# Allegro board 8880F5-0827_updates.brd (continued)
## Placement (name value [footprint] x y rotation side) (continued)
NOREF#1969  -  []  165.8 185.42 90 top
NOREF#1970  -  []  284.36 272.1 90 top
NOREF#1971  -  []  339.65 265.86 90 top
NOREF#1972  -  []  184.47 173.11 0 top
NOREF#1973  -  []  165.8 158.5 0 top
NOREF#1974  -  []  166.06 216.47 90 top
NOREF#1975  -  []  272.55 245.18 0 top
NOREF#1976  -  []  419.4 171.64 0 top
NOREF#1977  -  []  302.32 144.15 0 top
NOREF#1978  -  []  378.33 209.11 0 top
NOREF#1979  -  []  250.74 224.72 0 top
NOREF#1980  -  []  327.25 265.55 0 top
NOREF#1981  -  []  298.13 274.06 0 top
NOREF#1982  -  []  201.91 172.56 90 top
NOREF#1983  -  []  167.7 215.35 90 top
NOREF#1984  -  []  303.15 211.32 90 top
NOREF#1985  -  []  263.31 164.74 0 top
NOREF#1986  -  []  184.47 219.75 90 top
NOREF#1987  -  []  221.56 171.46 0 top
NOREF#1988  -  []  352.24 243.59 90 top
NOREF#1989  -  []  312.42 146.05 0 top
NOREF#1990  -  []  194.09 173.86 90 top
NOREF#1991  -  []  451.64 179.06 0 top
NOREF#1992  -  []  271.34 182.64 0 top
NOREF#1993  -  []  309.21 187.61 0 top
NOREF#1994  -  []  109.96 238.84 0 top
NOREF#1995  -  []  330.74 164.72 0 top
NOREF#1996  -  []  100.73 238.84 0 top
NOREF#1997  -  []  167.7 187.92 90 top
NOREF#1998  -  []  115.61 219.13 90 top
NOREF#1999  -  []  468.01 171.53 0 top
NOREF#2000  -  []  254.61 205.86 90 top
NOREF#2001  -  []  230.43 188.88 0 top
NOREF#2002  -  []  275.12 271.65 90 top
NOREF#2003  -  []  326.43 288.31 90 top
NOREF#2004  -  []  329.85 164.74 0 top
NOREF#2005  -  []  346.27 132.97 90 top
NOREF#2006  -  []  295.96 248.49 0 top
NOREF#2007  -  []  262.04 164.74 0 top
NOREF#2008  -  []  200.98 255.15 90 top
NOREF#2009  -  []  230.73 193.69 0 top
NOREF#2010  -  []  450.03 182.17 0 top
NOREF#2011  -  []  383.09 273.11 0 top
NOREF#2012  -  []  328.42 129.74 90 top
NOREF#2013  -  []  118.45 234.24 90 top
NOREF#2014  -  []  331.62 205.55 0 top
NOREF#2015  -  []  342.04 164.72 0 top
NOREF#2016  -  []  259.65 265.86 90 top
NOREF#2017  -  []  471.21 175.95 90 top
NOREF#2018  -  []  306.92 154.05 0 top
NOREF#2019  -  []  463.61 171.53 0 top
NOREF#2020  -  []  182.57 240.28 0 top
NOREF#2021  -  []  216.96 180.71 0 top
NOREF#2022  -  []  259.33 205.55 0 top
NOREF#2023  -  []  115.99 130.36 90 top
NOREF#2024  -  []  334.29 204.35 90 top
NOREF#2025  -  []  463.11 186.77 0 top
NOREF#2026  -  []  237.66 224.74 0 top
NOREF#2027  -  []  124.1 238.84 0 top
NOREF#2028  -  []  343.2 232.26 90 top
NOREF#2029  -  []  330.73 264.35 90 top
NOREF#2030  -  []  419.9 288.57 90 top
NOREF#2031  -  []  248.96 224.74 0 top
NOREF#2032  -  []  247.25 265.56 90 top
NOREF#2033  -  []  396.55 241.11 0 top
NOREF#2034  -  []  184.89 254.6 90 top
NOREF#2035  -  []  106.76 215.26 0 top
NOREF#2036  -  []  239.33 176.03 0 top
NOREF#2037  -  []  165.8 144.78 0 top
NOREF#2038  -  []  192.47 168.6 90 top
NOREF#2039  -  []  209.49 177.76 90 top
NOREF#2040  -  []  312.67 146.1 90 top
NOREF#2041  -  []  226.83 209.63 90 top
NOREF#2042  -  []  312.79 288.86 90 top
NOREF#2043  -  []  339.65 264.65 90 top
NOREF#2044  -  []  418.37 289.17 90 top
NOREF#2045  -  []  352.25 243.59 90 top
NOREF#2046  -  []  351.34 245.18 0 top
NOREF#2047  -  []  333.33 241.33 90 top
NOREF#2048  -  []  209.49 168.6 90 top
NOREF#2049  -  []  468.85 257.36 90 top
NOREF#2050  -  []  398.53 178.25 90 top
NOREF#2051  -  []  230.73 249.2 0 top
NOREF#2052  -  []  249.6 223.52 90 top
NOREF#2053  -  []  310.73 253.69 0 top
NOREF#2054  -  []  396.55 225.11 0 top
NOREF#2055  -  []  344.37 128.27 0 top
NOREF#2056  -  []  471.59 130.36 90 top
NOREF#2057  -  []  264.29 143.19 0 top
NOREF#2058  -  []  332.51 205.55 0 top
NOREF#2059  -  []  334.29 205.56 90 top
NOREF#2060  -  []  272.55 249.5 0 top
NOREF#2061  -  []  226.27 216.63 90 top
NOREF#2062  -  []  185.2 276.04 90 top
NOREF#2063  -  []  175.7 218.65 90 top
NOREF#2064  -  []  378.75 256.66 90 top
NOREF#2065  -  []  108.01 222.33 0 top
NOREF#2066  -  []  320.42 131.64 0 top
NOREF#2067  -  []  192.47 259.8 90 top
NOREF#2068  -  []  418.37 241.16 90 top
NOREF#2069  -  []  555.66 300.54 90 top
NOREF#2070  -  []  310.83 224.63 0 top
NOREF#2071  -  []  165.8 212.85 0 top
NOREF#2072  -  []  392.47 272.56 90 top
NOREF#2073  -  []  254.29 205.56 0 top
NOREF#2074  -  []  333.33 181.33 90 top
NOREF#2075  -  []  253.4 265.56 0 top
NOREF#2076  -  []  249.15 296.86 0 top
NOREF#2077  -  []  352.25 249.18 90 top
NOREF#2078  -  []  310.73 249.2 0 top
NOREF#2079  -  []  329.85 224.74 0 top
NOREF#2080  -  []  201.23 219.75 90 top
NOREF#2081  -  []  369.38 257.11 0 top
NOREF#2082  -  []  199.84 175.58 90 top
NOREF#2083  -  []  93.76 271.33 90 top
NOREF#2084  -  []  250.18 182.88 0 top
NOREF#2085  -  []  423.71 181.22 90 top
NOREF#2086  -  []  263.31 224.74 0 top
NOREF#2087  -  []  351.34 249.5 0 top
NOREF#2088  -  []  405.93 272.56 90 top
NOREF#2089  -  []  313.77 146.05 90 top
NOREF#2090  -  []  310.73 193.69 0 top
NOREF#2091  -  []  229.51 243.41 0 top
NOREF#2092  -  []  175.7 205.19 90 top
NOREF#2093  -  []  199.59 230.19 90 top
NOREF#2094  -  []  259.59 133.29 90 top
NOREF#2095  -  []  267.84 280.1 0 top
NOREF#2096  -  []  224.65 211.67 0 top
NOREF#2097  -  []  310.41 188.88 90 top
NOREF#2098  -  []  118.74 215.34 0 top
NOREF#2099  -  []  298.13 214.06 0 top
NOREF#2100  -  []  165.8 199.39 90 top
NOREF#2101  -  []  265.64 280.1 0 top
NOREF#2102  -  []  237.98 163.82 90 top
NOREF#2103  -  []  412.6 161.74 0 top
NOREF#2104  -  []  199.33 240.28 90 top
NOREF#2105  -  []  184.47 229.07 90 top
NOREF#2106  -  []  284.36 280.1 0 top
NOREF#2107  -  []  450.03 166.93 0 top
NOREF#2108  -  []  201.23 242.78 90 top
NOREF#2109  -  []  263.71 288.86 0 top
NOREF#2110  -  []  262.36 223.82 90 top
NOREF#2111  -  []  220.36 237.06 0 top
NOREF#2112  -  []  400.34 194.68 90 top
NOREF#2113  -  []  93.02 247.21 90 top
NOREF#2114  -  []  309.51 253.69 0 top
NOREF#2115  -  []  259.33 204.35 90 top
NOREF#2116  -  []  252.6 296.86 0 top
NOREF#2117  -  []  264.29 280.1 0 top
NOREF#2118  -  []  230.41 248.88 90 top
NOREF#2119  -  []  175.8 228.97 90 top
NOREF#2120  -  []  331.54 192.73 90 top
NOREF#2121  -  []  271.34 181.37 0 top
NOREF#2122  -  []  328.96 164.74 0 top
NOREF#2123  -  []  392.47 288.67 90 top
NOREF#2124  -  []  332.51 265.56 90 top
NOREF#2125  -  []  388.43 180.15 0 top
NOREF#2126  -  []  226.83 269.63 90 top
NOREF#2127  -  []  399.67 139.89 0 top
NOREF#2128  -  []  328.96 164.72 0 top
NOREF#2129  -  []  371.48 257.11 0 top
NOREF#2130  -  []  263.63 163.82 90 top
NOREF#2131  -  []  479.44 239.09 0 top
NOREF#2132  -  []  333.72 205.86 90 top
NOREF#2133  -  []  101.82 271.33 90 top
NOREF#2134  -  []  451.68 230.2 0 top
NOREF#2135  -  []  402.06 217.61 0 top
NOREF#2136  -  []  222.11 240.71 0 top
NOREF#2137  -  []  456.08 214.96 0 top
NOREF#2138  -  []  266.49 143.19 0 top
NOREF#2139  -  []  371.73 273.11 0 top
NOREF#2140  -  []  320.94 211.63 90 top
NOREF#2141  -  []  385.19 241.11 0 top
NOREF#2142  -  []  375.73 196.98 90 top
NOREF#2143  -  []  380.53 217.11 0 top
NOREF#2144  -  []  334.29 265.56 0 top
NOREF#2145  -  []  366.88 222.7 0 top
NOREF#2146  -  []  475.04 239.09 0 top
NOREF#2147  -  []  247.89 204.35 90 top
NOREF#2148  -  []  387.39 297.12 0 top
NOREF#2149  -  []  106.76 222.88 0 top
NOREF#2150  -  []  485.36 257.36 90 top
NOREF#2151  -  []  331.94 204.65 90 top
NOREF#2152  -  []  249.6 224.74 90 top
NOREF#2153  -  []  411.09 146.88 90 top
NOREF#2154  -  []  317.83 197.63 0 top
NOREF#2155  -  []  406.44 154.88 0 top
NOREF#2156  -  []  397.55 209.41 90 top
NOREF#2157  -  []  378.75 224.05 90 top
NOREF#2158  -  []  107.02 179.19 0 top
NOREF#2159  -  []  182.82 243.9 90 top
NOREF#2160  -  []  378.58 273.11 90 top
NOREF#2161  -  []  511.59 293.82 90 top
NOREF#2162  -  []  312.21 131.64 0 top
NOREF#2163  -  []  418.37 273.42 90 top
NOREF#2164  -  []  208.98 259.8 90 top
NOREF#2165  -  []  168.69 292.55 90 top
NOREF#2166  -  []  385.32 178.25 90 top
NOREF#2167  -  []  241.6 296.61 0 top
NOREF#2168  -  []  215.96 237.06 0 top
NOREF#2169  -  []  220.36 248.49 0 top
NOREF#2170  -  []  167.7 145.93 90 top
NOREF#2171  -  []  106.18 160.58 90 top
NOREF#2172  -  []  410.78 131.89 0 top
NOREF#2173  -  []  473.79 196.21 0 top
NOREF#2174  -  []  105.58 234.24 90 top
NOREF#2175  -  []  177.33 133.47 90 top
NOREF#2176  -  []  420.62 287.22 90 top
NOREF#2177  -  []  182.57 144.78 90 top
NOREF#2178  -  []  182.82 203.01 90 top
NOREF#2179  -  []  251.86 192.43 90 top
NOREF#2180  -  []  263.95 223.52 90 top
NOREF#2181  -  []  403.41 209.61 0 top
NOREF#2182  -  []  305.83 204.31 0 top
NOREF#2183  -  []  401.87 139.89 0 top
NOREF#2184  -  []  185.2 292.55 90 top
NOREF#2185  -  []  453.88 171.53 0 top
NOREF#2186  -  []  342.36 165.04 90 top
NOREF#2187  -  []  311.15 159.63 90 top
NOREF#2188  -  []  392.73 188.15 0 top
NOREF#2189  -  []  342.04 224.74 0 top
NOREF#2190  -  []  182.82 175.58 90 top
NOREF#2191  -  []  230.43 194.01 0 top
NOREF#2192  -  []  184.47 176.66 90 top
NOREF#2193  -  []  396.55 289.12 0 top
NOREF#2194  -  []  111.54 287.84 90 top
NOREF#2195  -  []  128.05 273.87 90 top
NOREF#2196  -  []  167.7 132.72 0 top
NOREF#2197  -  []  272.25 184.23 0 top
NOREF#2198  -  []  392.73 154.88 0 top
NOREF#2199  -  []  200.98 256.5 90 top
NOREF#2200  -  []  310.41 247.61 90 top
NOREF#2201  -  []  328.33 187.93 0 top
NOREF#2202  -  []  388.66 139.89 0 top
NOREF#2203  -  []  399.39 178.25 0 top
NOREF#2204  -  []  175.7 209.49 90 top
NOREF#2205  -  []  230.41 188.88 90 top
NOREF#2206  -  []  273.09 288.31 90 top
NOREF#2207  -  []  352.24 182.32 90 top
NOREF#2208  -  []  472.86 210.36 90 top
NOREF#2209  -  []  320.94 151.63 90 top
NOREF#2210  -  []  383.09 224.85 0 top
NOREF#2211  -  []  101.82 273.87 90 top
NOREF#2212  -  []  327.15 286.96 90 top
NOREF#2213  -  []  155.57 275.14 90 top
NOREF#2214  -  []  468.01 214.96 0 top
NOREF#2215  -  []  297.83 174.63 90 top
NOREF#2216  -  []  225.83 204.31 0 top
NOREF#2217  -  []  248.33 247.93 0 top
NOREF#2218  -  []  461.86 225.6 90 top
NOREF#2219  -  []  118.33 273.87 90 top
NOREF#2220  -  []  338.2 246.67 0 top
NOREF#2221  -  []  201.49 176.66 90 top
NOREF#2222  -  []  369.38 241.11 0 top
NOREF#2223  -  []  310.73 189.2 0 top
NOREF#2224  -  []  397.8 179.6 90 top
NOREF#2225  -  []  460.93 234.74 90 top
NOREF#2226  -  []  331.62 204.35 90 top
NOREF#2227  -  []  201.23 227.72 90 top
NOREF#2228  -  []  451.68 195.91 0 top
NOREF#2229  -  []  167.7 134.07 90 top
NOREF#2230  -  []  320.83 194.63 0 top
NOREF#2231  -  []  239.33 183.63 90 top
NOREF#2232  -  []  411.26 163.19 90 top
NOREF#2233  -  []  409.17 281.37 0 top
NOREF#2234  -  []  117.33 247.35 90 top
NOREF#2235  -  []  318.3 164.74 90 top
NOREF#2236  -  []  250.74 164.72 0 top
NOREF#2237  -  []  379.73 271.21 90 top
NOREF#2238  -  []  465.45 292.92 90 top
NOREF#2239  -  []  209.33 215.25 90 top
NOREF#2240  -  []  403.41 209.61 0 top
NOREF#2241  -  []  306.85 271.67 0 top
NOREF#2242  -  []  322.62 139.64 0 top
NOREF#2243  -  []  392.24 199.18 90 top
NOREF#2244  -  []  386.53 181.42 90 top
NOREF#2245  -  []  339.33 265.55 0 top
NOREF#2246  -  []  230.73 243.41 0 top
NOREF#2247  -  []  528.1 257.36 90 top
NOREF#2248  -  []  263.83 231.63 90 top
NOREF#2249  -  []  119.76 127 90 top
NOREF#2250  -  []  423.2 146.88 0 top
NOREF#2251  -  []  334.61 264.65 90 top
NOREF#2252  -  []  483.04 239.09 0 top
NOREF#2253  -  []  415.1 163.64 0 top
NOREF#2254  -  []  201.23 201.89 90 top
NOREF#2255  -  []  411.26 179.6 90 top
NOREF#2256  -  []  250.74 224.74 0 top
NOREF#2257  -  []  352.55 242.64 0 top
NOREF#2258  -  []  177.33 187.32 90 top
NOREF#2259  -  []  409.17 297.12 0 top
NOREF#2260  -  []  167.7 165.4 90 top
NOREF#2261  -  []  424.55 146.88 90 top
NOREF#2262  -  []  394.05 255.47 0 top
NOREF#2263  -  []  238.3 224.74 90 top
NOREF#2264  -  []  106.76 210.11 90 top
NOREF#2265  -  []  229.51 183.41 0 top
NOREF#2266  -  []  398.53 161.74 90 top
NOREF#2267  -  []  118.7 182.93 90 top
NOREF#2268  -  []  339.33 265.55 0 top
NOREF#2269  -  []  387.8 210.63 90 top
NOREF#2270  -  []  230.73 253.69 0 top
NOREF#2271  -  []  201.23 200.54 90 top
NOREF#2272  -  []  249.6 164.74 90 top
NOREF#2273  -  []  200.98 260.9 90 top
NOREF#2274  -  []  409.74 146.88 0 top
NOREF#2275  -  []  272.24 183.59 90 top
NOREF#2276  -  []  217.41 213.24 0 top
NOREF#2277  -  []  167.7 241.43 0 top
NOREF#2278  -  []  209.23 236.67 90 top
NOREF#2279  -  []  201.66 213.45 90 top
NOREF#2280  -  []  314.55 286.96 0 top
NOREF#2281  -  []  211.11 146.93 90 top
NOREF#2282  -  []  184.47 145.93 0 top
NOREF#2283  -  []  398.65 297.12 0 top
NOREF#2284  -  []  272.24 181.05 90 top
NOREF#2285  -  []  251.62 264.35 90 top
NOREF#2286  -  []  127.7 231.22 0 top
NOREF#2287  -  []  252.83 205.86 90 top
NOREF#2288  -  []  260.6 286.96 90 top
NOREF#2289  -  []  471.21 211.76 90 top
NOREF#2290  -  []  167.7 145.93 0 top
NOREF#2291  -  []  118.45 231.77 0 top
NOREF#2292  -  []  378.33 241.11 90 top
NOREF#2293  -  []  312.46 131.69 90 top
NOREF#2294  -  []  194.09 214.75 90 top
NOREF#2295  -  []  104.18 191.95 0 top
NOREF#2296  -  []  310.43 183.09 90 top
NOREF#2297  -  []  192.47 148.38 90 top
NOREF#2298  -  []  341.48 286.96 0 top
NOREF#2299  -  []  166.06 243.9 90 top
NOREF#2300  -  []  201.91 145.63 90 top
NOREF#2301  -  []  184.47 256.5 90 top
NOREF#2302  -  []  273.5 148.65 90 top
NOREF#2303  -  []  254.61 265.86 90 top
NOREF#2304  -  []  271.04 249.82 0 top
NOREF#2305  -  []  352.25 241.69 0 top
NOREF#2306  -  []  459.24 219.3 0 top
NOREF#2307  -  []  415.61 185.72 90 top
NOREF#2308  -  []  292.74 288.86 0 top
NOREF#2309  -  []  328.62 290.13 90 top
NOREF#2310  -  []  346.08 288.86 0 top
NOREF#2311  -  []  201.23 247.18 90 top
NOREF#2312  -  []  387.39 232.85 0 top
NOREF#2313  -  []  460.89 217.9 90 top
NOREF#2314  -  []  108.27 178.64 0 top
NOREF#2315  -  []  272.25 242.96 0 top
NOREF#2316  -  []  410.27 257.37 0 top
NOREF#2317  -  []  388.43 163.64 0 top
NOREF#2318  -  []  331.86 192.43 90 top
NOREF#2319  -  []  127.95 222.33 0 top
NOREF#2320  -  []  298.16 177.06 0 top
NOREF#2321  -  []  368.03 249.11 0 top
NOREF#2322  -  []  167.7 178.86 90 top
NOREF#2323  -  []  451.68 186.77 0 top
NOREF#2324  -  []  182.57 226.57 90 top
NOREF#2325  -  []  209.23 246.08 90 top
NOREF#2326  -  []  399.99 181.42 90 top
NOREF#2327  -  []  218.16 237.06 0 top
NOREF#2328  -  []  306.71 139.64 0 top
NOREF#2329  -  []  366.88 255.21 0 top
NOREF#2330  -  []  251.06 165.04 90 top
NOREF#2331  -  []  396.55 273.11 0 top
NOREF#2332  -  []  397.38 163.64 90 top
NOREF#2333  -  []  317.57 269.63 90 top
NOREF#2334  -  []  230.43 248.88 90 top
NOREF#2335  -  []  412.62 281.37 0 top
NOREF#2336  -  []  330.51 288.86 0 top
NOREF#2337  -  []  215.96 188.49 0 top
NOREF#2338  -  []  389.7 209.36 0 top
NOREF#2339  -  []  127.55 219.13 90 top
NOREF#2340  -  []  259.65 205.86 90 top
NOREF#2341  -  []  262.68 164.74 90 top
NOREF#2342  -  []  302.11 192.14 0 top
NOREF#2343  -  []  242.23 173.13 90 top
NOREF#2344  -  []  459.24 219.3 90 top
NOREF#2345  -  []  343.2 172.26 90 top
NOREF#2346  -  []  272.8 157.28 0 top
NOREF#2347  -  []  450.03 210.36 0 top
NOREF#2348  -  []  251.62 205.55 0 top
NOREF#2349  -  []  316.43 132.91 90 top
NOREF#2350  -  []  511.59 291.28 90 top
NOREF#2351  -  []  247.25 205.55 0 top
NOREF#2352  -  []  184.47 159.65 90 top
NOREF#2353  -  []  272.25 181.69 0 top
NOREF#2354  -  []  332.51 205.56 90 top
NOREF#2355  -  []  35.83 128.17 90 top
NOREF#2356  -  []  451.68 214.96 0 top
NOREF#2357  -  []  450.03 166.93 0 top
NOREF#2358  -  []  230.43 248.88 0 top
NOREF#2359  -  []  271.34 243.91 0 top
NOREF#2360  -  []  260.83 174.63 90 top
NOREF#2361  -  []  259.65 204.65 90 top
NOREF#2362  -  []  377.32 171.39 0 top
NOREF#2363  -  []  230.43 247.61 0 top
NOREF#2364  -  []  388.43 146.88 0 top
NOREF#2365  -  []  230.41 187.61 90 top
NOREF#2366  -  []  270.04 135.24 90 top
NOREF#2367  -  []  333.4 205.56 0 top
NOREF#2368  -  []  410.52 289.12 0 top
NOREF#2369  -  []  419.9 154.88 0 top
NOREF#2370  -  []  256.77 163.82 90 top
NOREF#2371  -  []  415.1 163.64 0 top
NOREF#2372  -  []  263.85 273.37 90 top
NOREF#2373  -  []  379.01 272.66 90 top
NOREF#2374  -  []  461.86 187.32 0 top
NOREF#2375  -  []  184.47 178.86 90 top
NOREF#2376  -  []  118.45 226.62 90 top
NOREF#2377  -  []  354.27 134.07 90 top
NOREF#2378  -  []  410.52 273.37 0 top
NOREF#2379  -  []  317.98 225.04 90 top
NOREF#2380  -  []  552.76 299.72 0 top
NOREF#2381  -  []  388.43 146.88 0 top
NOREF#2382  -  []  273.81 286.96 90 top
NOREF#2383  -  []  331.22 253.63 0 top
NOREF#2384  -  []  259.65 204.65 90 top
NOREF#2385  -  []  254.29 205.56 90 top
NOREF#2386  -  []  393.19 271.21 90 top
NOREF#2387  -  []  331.06 163.82 90 top
NOREF#2388  -  []  405.17 131.89 0 top
NOREF#2389  -  []  237.83 197.63 0 top
NOREF#2390  -  []  182.82 257.62 90 top
NOREF#2391  -  []  201.23 241.43 0 top
NOREF#2392  -  []  330.73 265.56 0 top
NOREF#2393  -  []  459.28 211.76 90 top
NOREF#2394  -  []  273.95 155.38 0 top
NOREF#2395  -  []  66.26 290.38 90 top
NOREF#2396  -  []  408.92 265.37 0 top
NOREF#2397  -  []  405.93 224.66 90 top
NOREF#2398  -  []  175.8 147.18 90 top
NOREF#2399  -  []  403.41 209.61 0 top
NOREF#2400  -  []  392.04 273.11 90 top
NOREF#2401  -  []  390.69 273.11 0 top
NOREF#2402  -  []  401.87 194.18 90 top
NOREF#2403  -  []  250.73 265.56 90 top
NOREF#2404  -  []  201.23 241.43 90 top
NOREF#2405  -  []  352.24 184.86 90 top
NOREF#2406  -  []  120.24 171.1 0 top
NOREF#2407  -  []  390.53 188.15 0 top
NOREF#2408  -  []  289.01 272.1 0 top
NOREF#2409  -  []  404.4 289.17 90 top
NOREF#2410  -  []  262.36 163.82 90 top
NOREF#2411  -  []  369.38 257.11 0 top
NOREF#2412  -  []  257.9 186.35 90 top
NOREF#2413  -  []  413.71 178.82 0 top
NOREF#2414  -  []  375.22 163.39 0 top
NOREF#2415  -  []  184.47 206.29 90 top
NOREF#2416  -  []  22.16 130.26 90 top
NOREF#2417  -  []  285.71 280.1 0 top
NOREF#2418  -  []  451.68 171.53 0 top
NOREF#2419  -  []  330.18 182.88 0 top
NOREF#2420  -  []  392.47 288.57 90 top
NOREF#2421  -  []  257.09 164.74 90 top
NOREF#2422  -  []  262.04 164.72 0 top
NOREF#2423  -  []  199.33 199.39 90 top
NOREF#2424  -  []  108.01 214.71 0 top
NOREF#2425  -  []  413.1 144.98 0 top
NOREF#2426  -  []  165.8 144.78 90 top
NOREF#2427  -  []  284.79 272.65 90 top
NOREF#2428  -  []  192.47 246.08 90 top
NOREF#2429  -  []  390.53 146.88 0 top
NOREF#2430  -  []  201.91 159.1 90 top
NOREF#2431  -  []  419.22 257.37 90 top
NOREF#2432  -  []  378.75 256.56 90 top
NOREF#2433  -  []  209.49 164.3 90 top
NOREF#2434  -  []  404.15 225.11 0 top
NOREF#2435  -  []  322.23 233.13 0 top
NOREF#2436  -  []  256.45 224.74 0 top
NOREF#2437  -  []  331.62 205.56 0 top
NOREF#2438  -  []  462.06 293.82 90 top
NOREF#2439  -  []  380.59 271.21 0 top
NOREF#2440  -  []  405.5 257.37 90 top
NOREF#2441  -  []  209.23 232.37 90 top
NOREF#2442  -  []  336.77 223.82 90 top
NOREF#2443  -  []  352.25 184.23 0 top
NOREF#2444  -  []  485.36 289.48 90 top
NOREF#2445  -  []  403.99 188.15 0 top
NOREF#2446  -  []  373.68 249.11 0 top
NOREF#2447  -  []  518.38 276.41 90 top
NOREF#2448  -  []  400.24 202.38 90 top
NOREF#2449  -  []  201.23 192.32 90 top
NOREF#2450  -  []  252.6 288.86 0 top
NOREF#2451  -  []  392.21 131.94 90 top
NOREF#2452  -  []  252.51 205.55 0 top
NOREF#2453  -  []  311.15 219.63 90 top
NOREF#2454  -  []  470.71 183.57 90 top
NOREF#2455  -  []  343.95 164.74 90 top
NOREF#2456  -  []  119.95 195.15 0 top
NOREF#2457  -  []  230.43 248.88 90 top
NOREF#2458  -  []  405.51 209.61 0 top
NOREF#2459  -  []  182.57 185.42 0 top
NOREF#2460  -  []  375.73 194.78 90 top
NOREF#2461  -  []  250.17 225.04 90 top
NOREF#2462  -  []  107.76 238.84 0 top
NOREF#2463  -  []  279.27 288.86 0 top
NOREF#2464  -  []  167.7 136.27 90 top
NOREF#2465  -  []  312.25 211.67 90 top
NOREF#2466  -  []  261.63 173.83 90 top
NOREF#2467  -  []  459.28 168.33 90 top
NOREF#2468  -  []  353.35 288.41 90 top
NOREF#2469  -  []  400.85 249.11 0 top
NOREF#2470  -  []  168.13 254.6 90 top
NOREF#2471  -  []  237.98 225.04 90 top
NOREF#2472  -  []  331.62 265.55 0 top
NOREF#2473  -  []  93.76 273.87 90 top
NOREF#2474  -  []  184.47 200.54 0 top
NOREF#2475  -  []  247.89 264.35 90 top
NOREF#2476  -  []  108.27 178.64 0 top
NOREF#2477  -  []  394 217.36 0 top
NOREF#2478  -  []  342.68 164.74 90 top
NOREF#2479  -  []  184.47 233.47 90 top
NOREF#2480  -  []  117.26 190.55 90 top
NOREF#2481  -  []  167.7 260.9 90 top
NOREF#2482  -  []  184.47 258.7 90 top
NOREF#2483  -  []  330.74 224.74 0 top
NOREF#2484  -  []  167.7 149.48 90 top
NOREF#2485  -  []  175.7 195.52 90 top
NOREF#2486  -  []  309.51 183.41 0 top
NOREF#2487  -  []  209.49 182.06 90 top
NOREF#2488  -  []  404.4 273.16 90 top
NOREF#2489  -  []  352.25 181.05 90 top
NOREF#2490  -  []  184.47 227.72 0 top
NOREF#2491  -  []  192.47 230.17 90 top
NOREF#2492  -  []  352.25 244.23 0 top
NOREF#2493  -  []  518.38 292.92 90 top
NOREF#2494  -  []  264.29 272.1 90 top
NOREF#2495  -  []  275.28 290.13 90 top
NOREF#2496  -  []  415.1 163.64 0 top
NOREF#2497  -  []  184.47 227.72 90 top
NOREF#2498  -  []  390.69 241.11 0 top
NOREF#2499  -  []  220.36 188.49 0 top
NOREF#2500  -  []  226.44 294.64 90 top
NOREF#2501  -  []  460.93 225.6 90 top
NOREF#2502  -  []  222.11 252.14 0 top
NOREF#2503  -  []  471.11 230.2 0 top
NOREF#2504  -  []  201.49 159.65 90 top
NOREF#2505  -  []  252.51 205.56 90 top
NOREF#2506  -  []  211.11 160.4 90 top
NOREF#2507  -  []  319.33 176.03 0 top
NOREF#2508  -  []  343.83 171.63 90 top
NOREF#2509  -  []  110.47 171.02 0 top
NOREF#2510  -  []  411.52 146.43 90 top
NOREF#2511  -  []  247.25 205.56 0 top
NOREF#2512  -  []  250.73 264.35 90 top
NOREF#2513  -  []  330.51 288.86 0 top
NOREF#2514  -  []  209.23 191.22 90 top
NOREF#2515  -  []  554.86 298.45 0 top
NOREF#2516  -  []  395.2 249.11 0 top
NOREF#2517  -  []  376.23 209.11 0 top
NOREF#2518  -  []  201.49 151.93 90 top
NOREF#2519  -  []  448.94 292.92 90 top
NOREF#2520  -  []  229.21 186.34 0 top
NOREF#2521  -  []  330.74 224.72 0 top
NOREF#2522  -  []  167.7 255.15 0 top
NOREF#2523  -  []  518.38 290.38 90 top
NOREF#2524  -  []  244.8 288.61 0 top
NOREF#2525  -  []  379.48 239.21 90 top
NOREF#2526  -  []  201.23 200.54 0 top
NOREF#2527  -  []  199.08 254 0 top
NOREF#2528  -  []  271.04 241.69 0 top
NOREF#2529  -  []  346.27 129.42 0 top
NOREF#2530  -  []  194.09 201.29 90 top
NOREF#2531  -  []  318.32 131.64 0 top
NOREF#2532  -  []  310.83 164.63 0 top
NOREF#2533  -  []  256.77 223.82 90 top
NOREF#2534  -  []  310.43 188.88 90 top
NOREF#2535  -  []  327.57 204.65 90 top
NOREF#2536  -  []  253.4 205.56 0 top
NOREF#2537  -  []  405.5 289.12 90 top
NOREF#2538  -  []  518.38 273.87 90 top
NOREF#2539  -  []  371.73 289.12 0 top
NOREF#2540  -  []  398.65 241.11 0 top
NOREF#2541  -  []  413.75 171.64 0 top
NOREF#2542  -  []  472.86 166.93 90 top
NOREF#2543  -  []  390.53 154.88 0 top
NOREF#2544  -  []  249.85 224.72 0 top
NOREF#2545  -  []  119.7 231.22 0 top
NOREF#2546  -  []  127.55 184.33 90 top
NOREF#2547  -  []  342.68 224.74 90 top
NOREF#2548  -  []  397.3 209.36 0 top
NOREF#2549  -  []  310.43 193.37 90 top
NOREF#2550  -  []  121.9 231.22 0 top
NOREF#2551  -  []  167.7 227.72 0 top
NOREF#2552  -  []  259.65 264.65 90 top
NOREF#2553  -  []  329.85 224.72 0 top
NOREF#2554  -  []  259.65 264.65 90 top
NOREF#2555  -  []  262.36 165.04 90 top
NOREF#2556  -  []  215.96 177.06 0 top
NOREF#2557  -  []  168.69 273.5 90 top
NOREF#2558  -  []  201.23 215.35 90 top
NOREF#2559  -  []  334.29 205.55 0 top
NOREF#2560  -  []  192.47 182.06 90 top
NOREF#2561  -  []  339.89 288.41 90 top
NOREF#2562  -  []  168.13 199.99 90 top
NOREF#2563  -  []  339.33 205.55 0 top
NOREF#2564  -  []  371.48 265.11 0 top
NOREF#2565  -  []  230.43 188.88 90 top
NOREF#2566  -  []  261.21 286.96 0 top
NOREF#2567  -  []  118.7 217.73 90 top
NOREF#2568  -  []  118.7 195.7 0 top
NOREF#2569  -  []  412.79 209.06 90 top
NOREF#2570  -  []  310.43 187.61 0 top
NOREF#2571  -  []  184.47 187.92 90 top
NOREF#2572  -  []  201.21 292.55 90 top
R1  NC/1M-1-S4  [R0402]  221.23 227.84 180 bottom
R2  NC/1M-1-S4  [R0402]  218.95 227.84 0 bottom
R3  NC/100K-1-S4  [R0402]  184.15 131.06 180 bottom
R4  NC/100K-1-S4  [R0402]  181.61 131.06 180 bottom
R5  0-5-S4  [R0402]  222.38 272.16 270 bottom
R6  1M-1-S4  [R0402]  222.38 274.32 270 bottom
R7  49.9-1-S4  [R0402]  349.4 299.66 180 bottom
R8  49.9-1-S4  [R0402]  351.55 299.66 180 bottom
R9  49.9-1-S4  [R0402]  349.4 286.07 180 bottom
R10  49.9-1-S4  [R0402]  351.55 286.07 180 bottom
R11  49.9-1-S4  [R0402]  335.94 299.66 180 bottom
R12  49.9-1-S4  [R0402]  338.09 299.66 180 bottom
R13  49.9-1-S4  [R0402]  335.94 286.07 180 bottom
R14  49.9-1-S4  [R0402]  338.09 286.07 180 bottom
R15  49.9-1-S4  [R0402]  322.48 299.66 180 bottom
R16  49.9-1-S4  [R0402]  324.62 299.66 180 bottom
R17  49.9-1-S4  [R0402]  322.48 286.07 180 bottom
R18  49.9-1-S4  [R0402]  324.62 286.07 180 bottom
R19  49.9-1-S4  [R0402]  287.88 269.3 0 bottom
R20  49.9-1-S4  [R0402]  285.74 269.3 0 bottom
R21  49.9-1-S4  [R0402]  287.88 282.89 0 bottom
R22  49.9-1-S4  [R0402]  285.74 282.89 0 bottom
R23  49.9-1-S4  [R0402]  309.27 299.66 180 bottom
R24  49.9-1-S4  [R0402]  311.42 299.66 180 bottom
R25  49.9-1-S4  [R0402]  309.27 286.07 180 bottom
R26  49.9-1-S4  [R0402]  311.42 286.07 180 bottom
R27  49.9-1-S4  [R0402]  296.06 299.66 180 bottom
R28  49.9-1-S4  [R0402]  298.21 299.66 180 bottom
R29  49.9-1-S4  [R0402]  296.06 286.07 180 bottom
R30  49.9-1-S4  [R0402]  298.21 286.07 180 bottom
R31  49.9-1-S4  [R0402]  282.6 299.66 180 bottom
R32  49.9-1-S4  [R0402]  284.75 299.66 180 bottom
R33  49.9-1-S4  [R0402]  282.6 286.07 180 bottom
R34  49.9-1-S4  [R0402]  284.75 286.07 180 bottom
R37  49.9-1-S4  [R0402]  269.14 286.07 180 bottom
R38  49.9-1-S4  [R0402]  271.28 286.07 180 bottom
R39  49.9-1-S4  [R0402]  255.93 299.66 180 bottom
R40  49.9-1-S4  [R0402]  258.08 299.66 180 bottom
R41  49.9-1-S4  [R0402]  255.93 286.07 180 bottom
R42  49.9-1-S4  [R0402]  258.08 286.07 180 bottom
R43  49.9-1-S4  [R0402]  164.91 258.67 90 bottom
R44  49.9-1-S4  [R0402]  164.91 256.53 90 bottom
R45  49.9-1-S4  [R0402]  198.44 231.24 90 bottom
R46  49.9-1-S4  [R0402]  198.44 229.1 90 bottom
R47  49.9-1-S4  [R0402]  178.5 217.52 90 bottom
R48  49.9-1-S4  [R0402]  178.5 215.38 90 bottom
R49  49.9-1-S4  [R0402]  164.91 217.52 90 bottom
R50  49.9-1-S4  [R0402]  164.91 215.38 90 bottom
R51  49.9-1-S4  [R0402]  195.26 231.24 90 bottom
R52  49.9-1-S4  [R0402]  195.26 229.1 90 bottom
R53  49.9-1-S4  [R0402]  181.67 231.24 90 bottom
R54  49.9-1-S4  [R0402]  181.67 229.1 90 bottom
R55  49.9-1-S4  [R0402]  212.03 244.96 90 bottom
R56  49.9-1-S4  [R0402]  212.03 242.81 90 bottom
R57  49.9-1-S4  [R0402]  198.44 244.96 90 bottom
R58  49.9-1-S4  [R0402]  198.44 242.81 90 bottom
R59  49.9-1-S4  [R0402]  178.5 231.24 90 bottom
R60  49.9-1-S4  [R0402]  178.5 229.1 90 bottom
R61  49.9-1-S4  [R0402]  164.91 231.24 90 bottom
R62  49.9-1-S4  [R0402]  164.91 229.1 90 bottom
R63  49.9-1-S4  [R0402]  178.5 244.96 90 bottom
R64  49.9-1-S4  [R0402]  178.5 242.81 90 bottom
R65  49.9-1-S4  [R0402]  181.67 244.96 90 bottom
R66  49.9-1-S4  [R0402]  181.67 242.81 90 bottom
R67  49.9-1-S4  [R0402]  239.37 285.81 0 bottom
R68  49.9-1-S4  [R0402]  237.22 285.81 0 bottom
R69  49.9-1-S4  [R0402]  239.37 299.4 0 bottom
R70  49.9-1-S4  [R0402]  237.22 299.4 0 bottom
R71  49.9-1-S4  [R0402]  195.26 258.67 90 bottom
R72  49.9-1-S4  [R0402]  195.26 256.53 90 bottom
R73  49.9-1-S4  [R0402]  181.67 258.67 90 bottom
R74  49.9-1-S4  [R0402]  181.67 256.53 90 bottom
R75  49.9-1-S4  [R0402]  211.77 258.67 90 bottom
R76  49.9-1-S4  [R0402]  211.77 256.53 90 bottom
R77  49.9-1-S4  [R0402]  198.18 258.67 90 bottom
R78  49.9-1-S4  [R0402]  198.18 256.53 90 bottom
R79  49.9-1-S4  [R0402]  178.5 258.67 90 bottom
R80  49.9-1-S4  [R0402]  178.5 256.53 90 bottom
R82  4.7K-1-S4-WA  [R0402]  122.62 241.1 180 bottom
R83  4.7K-1-S4-WA  [R0402]  96.77 233.43 180 bottom
R84  4.7K-1-S4-WA  [R0402]  96.77 241.05 180 bottom
R85  100K-1-S4  [R0402]  113.79 230.12 180 bottom
R86  4.7K-1-S4-WA  [R0402]  93.33 207.46 180 bottom
R87  4.7K-1-S4-WA  [R0402]  104.14 203.31 180 bottom
R88  4.7K-1-S4-WA  [R0402]  101.6 203.31 180 bottom
R89  4.7K-1-S4-WA  [R0402]  89.03 207.41 0 bottom
R90  4.7K-1-S4-WA  [R0402]  101.6 215.5 180 bottom
R91  4.7K-1-S4-WA  [R0402]  99.06 215.5 180 bottom
R92  4.7K-1-S4-WA  [R0402]  96.52 215.5 180 bottom
R93  4.7K-1-S4-WA  [R0402]  93.33 221.18 180 bottom
R94  4.7K-1-S4-WA  [R0402]  104.25 216.86 0 bottom
R95  4.7K-1-S4-WA  [R0402]  101.7 216.91 180 bottom
R96  4.7K-1-S4-WA  [R0402]  89.27 221.18 0 bottom
R97  4.7K-1-S4-WA  [R0402]  101.7 229.1 180 bottom
R98  4.7K-1-S4-WA  [R0402]  99.16 229.1 180 bottom
R99  4.7K-1-S4-WA  [R0402]  96.62 229.1 180 bottom
R100  49.9-1-S4  [R0402]  164.91 244.96 90 bottom
R101  49.9-1-S4  [R0402]  164.91 242.81 90 bottom
R102  49.9-1-S4  [R0402]  212.03 231.24 90 bottom
R103  49.9-1-S4  [R0402]  212.03 229.1 90 bottom
R104  49.9-1-S4  [R0402]  195.26 244.96 90 bottom
R105  49.9-1-S4  [R0402]  195.26 242.81 90 bottom
R117  1K-1-S4  [R0402]  127.2 241.1 180 bottom
R118  NC/0-5-S4  [R0402]  230.41 245.39 180 bottom
R119  4.7K-1-S4-WA  [R0402]  127.25 233.43 0 bottom
R120  4.7K-1-S4-WA  [R0402]  127.25 225.81 0 bottom
R125  0-5-S4  [R0402]  123.19 224.54 180 bottom
R126  0-5-S4  [R0402]  127.25 224.54 180 bottom
R127  0-5-S4  [R0402]  122.94 216.92 180 bottom
R128  0-5-S4  [R0402]  127.51 216.92 180 bottom
R129  0-5-S4  [R0402]  221.23 229.11 180 bottom
R130  0-5-S4  [R0402]  218.95 229.11 0 bottom
R131  50-0.1-S4-HF-VI  [R0402]  223.77 243.33 90 bottom
R132  50-0.1-S4-HF-VI  [R0402]  216.15 243.33 90 bottom
R133  0-5-S4  [R0402]  222.38 276.48 90 bottom
RB1  10K-1-S6  [R0603]  212.47 13.59 0 bottom
RB2  10K-1-S6  [R0603]  212.47 12.06 0 bottom
S1_I2C  HDR-4X1-MR-A  [JP_4P_100_R90_V1]  62.99 209.04 270 top
S1_RST_N  HDR-2X1-M  [JP_2P_100]  115.82 232.41 270 bottom
S2_I2C  HDR-4X1-MR-A  [JP_4P_100_R90_V1]  497.33 203.45 270 top
S2_RST_N  HDR-2X1-M  [JP_2P_100]  463.04 233.43 90 bottom
S3_I2C  HDR-4X1-MR-A  [JP_4P_100_R90_V1]  75.69 209.04 270 top
S3_RST_N  HDR-2X1-M  [JP_2P_100]  116.08 188.72 270 bottom
S4_I2C  HDR-4X1-MR-A  [JP_4P_100_R90_V1]  511.3 203.45 270 top
S4_RST_N  HDR-2X1-M  [JP_2P_100]  463.04 189.99 90 bottom
SB1  SHORT  [DEFAULT_SHORT_SMALL]  402.59 11.04 90 top
SB2  SHORT  [DEFAULT_SHORT_SMALL]  328.93 417.83 270 top
SB3  SHORT  [DEFAULT_SHORT_SMALL]  255.27 11.71 90 top
SB8  SHORT  [DEFAULT_SHORT_SMALL]  179.07 418.32 270 top
SCREW1  V93KMFHOLE  [PG_VG93K_F_FULLOUTLINE]  290.83 214.63 0 top
SH1  SHORT  [DEFAULT_SHORT_SMALL]  185.19 290.72 0 top
SH2  SHORT  [DEFAULT_SHORT_SMALL]  187.14 290.72 0 top
SH3  SHORT  [DEFAULT_SHORT_SMALL]  175.35 290.72 0 top
SH4  SHORT  [DEFAULT_SHORT_SMALL]  173.4 290.85 180 top
SH5  SHORT  [DEFAULT_SHORT_SMALL]  118.2 289.45 0 top
SH6  SHORT  [DEFAULT_SHORT_SMALL]  116.25 289.58 180 top
SH7  SHORT  [DEFAULT_SHORT_SMALL]  168.68 290.72 0 top
SH8  SHORT  [DEFAULT_SHORT_SMALL]  156.89 290.85 180 top
SH9  SHORT  [DEFAULT_SHORT_SMALL]  170.63 290.72 0 top
SH10  SHORT  [DEFAULT_SHORT_SMALL]  158.84 290.72 0 top
SH11  SHORT  [DEFAULT_SHORT_SMALL]  173.4 274.34 180 top
SH12  SHORT  [DEFAULT_SHORT_SMALL]  185.19 274.21 0 top
SH13  SHORT  [DEFAULT_SHORT_SMALL]  203.14 290.72 0 top
SH14  SHORT  [DEFAULT_SHORT_SMALL]  201.19 290.72 0 top
SH15  SHORT  [DEFAULT_SHORT_SMALL]  189.4 290.85 180 top
SH16  SHORT  [DEFAULT_SHORT_SMALL]  191.35 290.72 0 top
SH17  SHORT  [DEFAULT_SHORT_SMALL]  156.89 274.34 180 top
SH18  SHORT  [DEFAULT_SHORT_SMALL]  168.68 274.21 0 top
SH19  SHORT  [DEFAULT_SHORT_SMALL]  99.42 246.45 0 top
SH20  SHORT  [DEFAULT_SHORT_SMALL]  101.62 246.45 0 top
SH21  SHORT  [DEFAULT_SHORT_SMALL]  94.56 246.5 0 top
SH22  SHORT  [DEFAULT_SHORT_SMALL]  96.76 246.5 0 top
SH23  SHORT  [DEFAULT_SHORT_SMALL]  201.19 274.21 0 top
SH24  SHORT  [DEFAULT_SHORT_SMALL]  203.37 274.08 180 top
SH25  SHORT  [DEFAULT_SHORT_SMALL]  175.35 274.21 0 top
SH26  SHORT  [DEFAULT_SHORT_SMALL]  187.14 274.21 0 top
SH27  SHORT  [DEFAULT_SHORT_SMALL]  158.84 274.21 0 top
SH28  SHORT  [DEFAULT_SHORT_SMALL]  170.63 274.21 0 top
SITE1  CU/HX8880-F05-LQFP176-20X20  [SK_LQFP176P_0P4MM_JG_HX8880]  250.83 244.63 90 top
SITE2  CU/HX8880-F05-LQFP176-20X20  [SK_LQFP176P_0P4MM_JG_HX8880]  330.83 244.63 90 top
SITE3  CU/HX8880-F05-LQFP176-20X20  [SK_LQFP176P_0P4MM_JG_HX8880]  250.83 184.63 90 top
SITE4  CU/HX8880-F05-LQFP176-20X20  [SK_LQFP176P_0P4MM_JG_HX8880]  330.83 184.63 90 top
SKB  Socket_Base_M5_140x140  [SOCKET_BASE_140X140_565100]  290.83 214.63 0 top
TP_AUXVCC  TP01  [TP_040_T]  101.29 247.61 180 top
TP_AVDD11_RX  TP01  [TP_040_T]  158.96 292.1 180 top
TP_AVDD11_XTAL  TP01  [TP_040_T]  201.21 275.59 0 top
TP_AVDD18_RX  TP01  [TP_040_T]  168.7 292.1 0 top
TP_PLL_M_VDD33  TP01  [TP_040_T]  201.21 292.1 0 top
TP_PLL_TX_VDD33  TP01  [TP_040_T]  191.48 292.1 180 top
TP_VCC3V3  TP01  [TP_040_T]  96.42 247.66 180 top
TP_VDD_IO_33  TP01  [TP_040_T]  175.47 292.1 180 top
TP_VDD_TXREG_33_B  TP01  [TP_040_T]  168.7 275.59 0 top
TP_VDD_TXREG_33_T  TP01  [TP_040_T]  158.96 275.59 180 top
TP_VDDA_33_LV  TP01  [TP_040_T]  185.21 292.1 0 top
TP_VDDC_11  TP01  [TP_040_T]  118.32 290.83 180 top
TP_VDDTXPST_11_B  TP01  [TP_040_T]  185.21 275.59 0 top
TP_VDDTXPST_11_T  TP01  [TP_040_T]  175.47 275.59 180 top
TP_XTAL_IN  TP01  [TP_040_T]  226.85 271.67 0 top
TP_XTAL_OUT  TP01  [TP_040_T]  226.85 276.97 0 top
TPL1  TPL01  [TPL_040_014_TB]  73.41 239.01 0 top
TPL2  TPL01  [TPL_040_014_TB]  78.49 244.09 0 top
TPL3  TPL01  [TPL_040_014_TB]  68.33 228.85 0 top
TPL4  TPL01  [TPL_040_014_TB]  68.33 239.01 0 top
TPL5  TPL01  [TPL_040_014_TB]  73.41 244.09 0 top
TPL6  TPL01  [TPL_040_014_TB]  68.33 233.93 0 top
TPL7  TPL01  [TPL_040_014_TB]  78.49 233.93 0 top
TPL8  TPL01  [TPL_040_014_TB]  73.41 233.93 0 top
TPL9  TPL01  [TPL_040_014_TB]  68.33 244.09 0 top
TPL10  TPL01  [TPL_040_014_TB]  78.49 239.01 0 top
TPL11  TPL01  [TPL_040_014_TB]  73.41 218.69 0 top
TPL12  TPL01  [TPL_040_014_TB]  78.49 218.69 0 top
TPL13  TPL01  [TPL_040_014_TB]  83.57 223.77 0 top
TPL14  TPL01  [TPL_040_014_TB]  83.57 218.69 0 top
TPL15  TPL01  [TPL_040_014_TB]  73.41 228.85 0 top
TPL16  TPL01  [TPL_040_014_TB]  68.33 223.77 0 top
TPL17  TPL01  [TPL_040_014_TB]  68.33 218.69 0 top
TPL18  TPL01  [TPL_040_014_TB]  78.49 223.77 0 top
TPL19  TPL01  [TPL_040_014_TB]  73.41 223.77 0 top
TPL20  TPL01  [TPL_040_014_TB]  78.49 228.85 0 top
TPL21  TPL01  [TPL_040_014_TB]  452.63 249.17 0 top
TPL22  TPL01  [TPL_040_014_TB]  452.63 259.33 0 top
TPL23  TPL01  [TPL_040_014_TB]  452.63 264.41 0 top
TPL24  TPL01  [TPL_040_014_TB]  452.63 254.25 0 top
TPL25  TPL01  [TPL_040_014_TB]  452.63 244.09 0 top
TPL26  TPL01  [TPL_040_014_TB]  457.71 244.09 0 top
TPL27  TPL01  [TPL_040_014_TB]  452.63 269.49 0 top
TPL28  TPL01  [TPL_040_014_TB]  457.71 249.17 0 top
TPL29  TPL01  [TPL_040_014_TB]  457.71 269.49 0 top
TPL30  TPL01  [TPL_040_014_TB]  457.71 264.41 0 top
TPL31  TPL01  [TPL_040_014_TB]  457.71 259.33 0 top
TPL32  TPL01  [TPL_040_014_TB]  457.71 254.25 0 top
TPL33  TPL01  [TPL_040_014_TB]  462.79 244.09 0 top
TPL34  TPL01  [TPL_040_014_TB]  467.87 249.17 0 top
TPL35  TPL01  [TPL_040_014_TB]  467.87 244.09 0 top
TPL36  TPL01  [TPL_040_014_TB]  462.79 249.17 0 top
TPL37  TPL01  [TPL_040_014_TB]  462.79 269.49 0 top
TPL38  TPL01  [TPL_040_014_TB]  462.79 259.33 0 top
TPL39  TPL01  [TPL_040_014_TB]  462.79 254.25 0 top
TPL40  TPL01  [TPL_040_014_TB]  462.79 264.41 0 top
U1  SOLDER-DIP8-SOCKET  [DIP8_300X100_RLPIN]  104.66 205.54 90 bottom
U2  SOLDER-DIP8-SOCKET  [DIP8_300X100_RLPIN]  104.76 219.15 90 bottom
UB1  AT24C04C-SSHM-SO8  [SO8_215X127MM]  218.44 13.97 180 bottom
UF1  MX25L4006EM2I-12G-SOP8  [SOCKET_CODE]  104.66 205.54 270 top
UF2  MX25L4006EM2I-12G-SOP8  [SOCKET_CODE]  104.75 219.2 270 top
UNK2C3  0.1U-16-X-S4-MU  [C0402]  289.81 132.08 180 bottom
UNK2C4  0.1U-16-X-S4-MU  [C0402]  287.27 132.08 180 bottom
UNK2C5  22P-50-N-S4-AVX  [C0402]  301.21 277.48 90 bottom
UNK2C6  22P-50-N-S4-AVX  [C0402]  301.21 271.16 270 bottom
UNK2C7  0.1U-16-X-S4-MU  [C0402]  468.12 235.71 180 bottom
UNK2C8  0.1U-16-X-S4-MU  [C0402]  475.39 204.98 0 bottom
UNK2C9  0.1U-16-X-S4-MU  [C0402]  475.49 218.59 0 bottom
UNK2CA1  NC/10U-10-X6S-S6-MU  [C0603]  462.91 293.37 0 bottom
UNK2CA2  NC/47U-10-X5R-S8-TDK  [C0805]  463.02 295.27 0 bottom
UNK2CA3  NC/10U-10-X6S-S6-MU  [C0603]  451.49 293.37 180 bottom
UNK2CA4  NC/47U-10-X5R-S8-TDK  [C0805]  451.38 295.27 180 bottom
UNK2CA5  NC/10U-10-X6S-S6-MU  [C0603]  484.5 293.37 180 bottom
UNK2CA6  NC/47U-10-X5R-S8-TDK  [C0805]  484.4 295.27 180 bottom
UNK2CA7  NC/10U-10-X6S-S6-MU  [C0603]  462.91 276.86 0 bottom
UNK2CA8  NC/47U-10-X5R-S8-TDK  [C0805]  463.02 278.76 0 bottom
UNK2CA9  NC/10U-10-X6S-S6-MU  [C0603]  451.49 276.86 180 bottom
UNK2CA10  NC/47U-10-X5R-S8-TDK  [C0805]  451.38 278.76 180 bottom
UNK2CA11  NC/10U-10-X6S-S6-MU  [C0603]  495.93 276.86 0 bottom
UNK2CA12  NC/47U-10-X5R-S8-TDK  [C0805]  496.04 278.76 0 bottom
UNK2CA13  NC/47U-10-X5R-S8-TDK  [C0805]  479.53 295.27 0 bottom
UNK2CA14  NC/10U-10-X6S-S6-MU  [C0603]  479.42 293.37 0 bottom
UNK2CA15  NC/47U-10-X5R-S8-TDK  [C0805]  467.89 295.27 180 bottom
UNK2CA16  NC/10U-10-X6S-S6-MU  [C0603]  468 293.37 180 bottom
UNK2CA17  NC/47U-10-X5R-S8-TDK  [C0805]  479.53 278.76 0 bottom
UNK2CA18  NC/10U-10-X6S-S6-MU  [C0603]  479.42 276.86 0 bottom
UNK2CA19  NC/47U-10-X5R-S8-TDK  [C0805]  91.09 249.81 180 bottom
UNK2CA20  NC/10U-10-X6S-S6-MU  [C0603]  91.19 247.9 180 bottom
UNK2CA21  10U-10-X6S-S6-MU  [C0603]  462.91 290.83 0 bottom
UNK2CA22  10U-10-X6S-S6-MU  [C0603]  451.49 290.83 180 bottom
UNK2CA23  10U-10-X6S-S6-MU  [C0603]  484.5 290.83 180 bottom
UNK2CA24  10U-10-X6S-S6-MU  [C0603]  462.91 274.32 0 bottom
UNK2CA25  10U-10-X6S-S6-MU  [C0603]  451.49 274.32 180 bottom
UNK2CA26  10U-10-X6S-S6-MU  [C0603]  495.93 274.32 0 bottom
UNK2CA27  10U-10-X6S-S6-MU  [C0603]  479.42 290.83 0 bottom
UNK2CA28  10U-10-X6S-S6-MU  [C0603]  468 290.83 180 bottom
UNK2CA29  10U-10-X6S-S6-MU  [C0603]  479.42 274.32 0 bottom
UNK2CA30  NC/47U-10-X5R-S8-TDK  [C0805]  86.22 249.86 180 bottom
UNK2CA31  10U-10-X6S-S6-MU  [C0603]  86.32 247.96 180 bottom
UNK2CA32  NC/10U-10-X6S-S6-MU  [C0603]  512.44 293.37 0 bottom
UNK2CA33  NC/47U-10-X5R-S8-TDK  [C0805]  512.55 295.27 0 bottom
UNK2CA34  10U-10-X6S-S6-MU  [C0603]  512.44 290.83 0 bottom
UNK2CA35  NC/10U-10-X6S-S6-MU  [C0603]  484.5 276.86 180 bottom
UNK2CA36  NC/47U-10-X5R-S8-TDK  [C0805]  484.4 278.76 180 bottom
UNK2CA37  10U-10-X6S-S6-MU  [C0603]  484.5 274.32 180 bottom
UNK2CA38  NC/10U-10-X6S-S6-MU  [C0603]  468 276.86 180 bottom
UNK2CA39  NC/47U-10-X5R-S8-TDK  [C0805]  467.89 278.76 180 bottom
UNK2CA40  10U-10-X6S-S6-MU  [C0603]  468 274.32 180 bottom
UNK2CC1  0.47U-10-X6S-S2-TY  [C0201]  317.98 224.12 90 bottom
UNK2CC2  4.7U-10-X6T-S4-MU  [C0402]  316.32 222.4 270 bottom
UNK2CC4  0.47U-10-X6S-S2-TY  [C0201]  309.81 247.93 0 bottom
UNK2CC6  0.47U-10-X6S-S2-TY  [C0201]  330.17 224.12 90 bottom
UNK2CC7  0.47U-10-X6S-S2-TY  [C0201]  309.81 246.66 0 bottom
UNK2CC8  0.47U-10-X6S-S2-TY  [C0201]  343.63 224.12 90 bottom
UNK2CC9  0.47U-10-X6S-S2-TY  [C0201]  334.61 266.16 270 bottom
UNK2CC11  0.47U-10-X6S-S2-TY  [C0201]  331.06 224.12 90 bottom
UNK2CC13  0.47U-10-X6S-S2-TY  [C0201]  336.77 224.12 90 bottom
UNK2CC15  4.7U-2.5-X6S-S2-MU  [C0201]  339.65 264.95 90 bottom
UNK2CC16  NC/4.7U-2.5-X6S-S2-MU  [C0201]  351.64 249.5 0 bottom
UNK2CC17  4.7U-2.5-X6S-S2-MU  [C0201]  309.81 253.69 0 bottom
UNK2CC19  0.47U-10-X6S-S2-TY  [C0201]  332.83 266.16 270 bottom
UNK2CC20  4.7U-10-X6T-S4-MU  [C0402]  334.11 267.66 0 bottom
UNK2CC22  0.47U-10-X6S-S2-TY  [C0201]  331.05 266.16 270 bottom
UNK2CC23  4.7U-10-X6T-S4-MU  [C0402]  330.34 253.09 270 bottom
UNK2CC25  0.47U-10-X6S-S2-TY  [C0201]  352.85 245.18 180 bottom
UNK2CC26  0.47U-10-X6S-S2-TY  [C0201]  333.72 266.16 270 bottom
UNK2CC27  0.47U-10-X6S-S2-TY  [C0201]  352.85 249.5 180 bottom
UNK2CC28  0.47U-10-X6S-S2-TY  [C0201]  339.65 266.16 270 bottom
UNK2CC29  0.47U-10-X6S-S2-TY  [C0201]  311.03 253.69 180 bottom
UNK2CC30  0.47U-10-X6S-S2-TY  [C0201]  309.81 243.41 0 bottom
UNK2CC31  0.47U-10-X6S-S2-TY  [C0201]  329.28 224.12 90 bottom
UNK2CC32  0.47U-10-X6S-S2-TY  [C0201]  342.36 224.12 90 bottom
UNK2CC33  0.47U-10-X6S-S2-TY  [C0201]  352.85 243.91 180 bottom
UNK2CC34  0.47U-10-X6S-S2-TY  [C0201]  331.94 266.16 270 bottom
UNK2CC35  0.47U-10-X6S-S2-TY  [C0201]  352.85 241.37 180 bottom
UNK2CC36  0.47U-10-X6S-S2-TY  [C0201]  352.85 242.64 180 bottom
UNK2CC37  0.47U-10-X6S-S2-TY  [C0201]  327.57 264.95 90 bottom
UNK2CC38  NC/4.7U-2.5-X6S-S2-MU  [C0201]  327.57 266.16 270 bottom
UNK2CC39  0.47U-10-X6S-S2-TY  [C0201]  311.03 249.2 180 bottom
UNK2CC40  4.7U-2.5-X6S-S2-MU  [C0201]  338.5 246.67 180 bottom
UNK2CC41  4.7U-2.5-X6S-S2-MU  [C0201]  309.81 249.2 0 bottom
UNK2CC42  4.7U-2.5-X6S-S2-MU  [C0201]  331.54 253.03 90 bottom
UNK2CD1  0.1U-10-X7R-S2-MU  [C0201]  317.98 225.34 270 top
UNK2CD3  0.1U-10-X7R-S2-MU  [C0201]  351.64 241.37 0 top
UNK2CD4  0.1U-10-X7R-S2-MU  [C0201]  334.61 264.95 90 top
UNK2CD5  0.1U-10-X7R-S2-MU  [C0201]  343.63 225.34 270 top
UNK2CD6  0.1U-10-X7R-S2-MU  [C0201]  311.03 246.66 180 top
UNK2CD7  0.1U-10-X7R-S2-MU  [C0201]  351.64 242.64 0 top
UNK2CD8  0.1U-10-X7R-S2-MU  [C0201]  331.06 225.34 270 top
UNK2CD9  0.1U-10-X7R-S2-MU  [C0201]  336.77 225.34 270 top
UNK2CD10  0.1U-10-X7R-S2-MU  [C0201]  351.64 249.5 0 top
UNK2CD11  0.1U-10-X7R-S2-MU  [C0201]  339.65 264.95 90 top
UNK2CD12  0.1U-10-X7R-S2-MU  [C0201]  311.03 253.69 180 top
UNK2CD13  0.1U-10-X7R-S2-MU  [C0201]  332.83 264.95 90 top
UNK2CD14  0.1U-10-X7R-S2-MU  [C0201]  331.05 264.95 90 top
UNK2CD15  0.1U-10-X7R-S2-MU  [C0201]  351.64 245.18 0 top
UNK2CD16  0.1U-10-X7R-S2-MU  [C0201]  333.72 264.95 90 top
UNK2CD17  0.1U-10-X7R-S2-MU  [C0201]  311.03 247.93 180 top
UNK2CD18  0.1U-10-X7R-S2-MU  [C0201]  331.94 264.95 90 top
UNK2CD19  0.1U-10-X7R-S2-MU  [C0201]  311.03 243.41 180 top
UNK2CD20  0.1U-10-X7R-S2-MU  [C0201]  351.64 243.91 0 top
UNK2CD21  0.1U-10-X7R-S2-MU  [C0201]  342.36 225.34 270 top
UNK2CD22  0.1U-10-X7R-S2-MU  [C0201]  329.28 225.34 270 top
UNK2CD23  0.1U-10-X7R-S2-MU  [C0201]  330.17 225.34 270 top
UNK2CD24  0.1U-10-X7R-S2-MU  [C0201]  327.57 264.95 90 top
UNK2CD25  0.1U-10-X7R-S2-MU  [C0201]  311.03 249.2 180 top
UNK2GND1  TP01  [TP_040_T]  450.43 295.27 0 top
UNK2GND2  TP01  [TP_040_T]  463.97 295.27 180 top
UNK2GND3  TP01  [TP_040_T]  483.45 295.27 0 top
UNK2GND4  TP01  [TP_040_T]  450.43 278.76 0 top
UNK2GND5  TP01  [TP_040_T]  463.97 278.76 180 top
UNK2GND6  TP01  [TP_040_T]  483.45 278.76 0 top
UNK2GND7  TP01  [TP_040_T]  480.48 295.27 180 top
UNK2GND8  TP01  [TP_040_T]  466.94 295.27 0 top
UNK2GND9  TP01  [TP_040_T]  480.48 278.76 180 top
UNK2GND10  TP01  [TP_040_T]  90.11 249.76 0 top
UNK2GND11  TP01  [TP_040_T]  85.24 249.81 0 top
UNK2GND12  TP01  [TP_040_T]  513.5 295.27 180 top
UNK2GND13  TP01  [TP_040_T]  496.99 278.76 180 top
UNK2GND14  TP01  [TP_040_T]  466.94 278.76 0 top
UNK2J1  HDR-2X1-M  [JP_2P_100]  468.63 233.43 90 bottom
UNK2J2  HDR-3X1-M  [JP_3P_100]  490.87 228.66 270 bottom
UNK2J3  HDR-3X1-M  [JP_3P_100]  490.87 214.94 270 bottom
UNK2J4  HDR-2X1-M  [JP_2P_100]  483.11 243.33 270 bottom
UNK2J5  HDR-2X1-M  [JP_2P_100]  483.11 231.65 270 bottom
UNK2K1  G6K-2F-RF-T-5V-SPECIAL  [RL_G6K2FRT_8P_5V_GR]  414.27 293.12 0 bottom
UNK2K2  G6K-2F-RF-T-5V-SPECIAL  [RL_G6K2FRT_8P_5V_GR]  373.13 245.11 0 bottom
UNK2K3  G6K-2F-RF-T-5V-SPECIAL  [RL_G6K2FRT_8P_5V_GR]  400.3 261.37 0 bottom
UNK2K4  G6K-2F-RF-T-5V-SPECIAL  [RL_G6K2FRT_8P_5V_GR]  373.13 261.11 0 bottom
UNK2K5  G6K-2F-RF-T-5V-SPECIAL  [RL_G6K2FRT_8P_5V_GR]  414.02 261.37 0 bottom
UNK2K6  G6K-2F-RF-T-5V-SPECIAL  [RL_G6K2FRT_8P_5V_GR]  414.27 277.37 0 bottom
UNK2K7  G6K-2F-RF-T-5V-SPECIAL  [RL_G6K2FRT_8P_5V_GR]  400.3 277.11 0 bottom
UNK2K8  G6K-2F-RF-T-5V-SPECIAL  [RL_G6K2FRT_8P_5V_GR]  386.84 293.12 0 bottom
UNK2K9  UA2-5NJ-A-V3  [RL_NECUA2_5V_V3]  299.96 235.46 90 bottom
UNK2K10  UA2-5NJ-A-V3  [RL_NECUA2_5V_V3]  467.11 228.6 180 bottom
UNK2K11  G6K-2F-RF-T-5V-SPECIAL  [RL_G6K2FRT_8P_5V_GR]  386.84 277.11 0 bottom
UNK2K12  UA2-5NJ-A-V3  [RL_NECUA2_5V_V3]  299.96 246.89 90 bottom
UNK2K13  UA2-5NJ-A-V3  [RL_NECUA2_5V_V3]  455.68 228.6 0 bottom
UNK2K14  UA2-5NJ-A-V3  [RL_NECUA2_5V_V3]  467.61 213.36 0 bottom
UNK2K15  UA2-5NJ-A-V3  [RL_NECUA2_5V_V3]  455.64 220.9 0 bottom
UNK2K16  G6K-2F-RF-T-5V-SPECIAL  [RL_G6K2FRT_8P_5V_GR]  373.38 277.11 0 bottom
UNK2K17  G6K-2F-RF-T-5V-SPECIAL  [RL_G6K2FRT_8P_5V_GR]  400.3 293.12 0 bottom
UNK2K18  UB2-5NU-B  [RL_NECUB2_5V]  308.45 274.32 0 bottom
UNK2K19  UA2-5NJ-A-V3  [RL_NECUA2_5V_V3]  467.61 220.98 0 bottom
UNK2K20  UA2-5NJ-A-V3  [RL_NECUA2_5V_V3]  455.68 213.36 0 bottom
UNK2K21  G6K-2F-RF-T-5V-SPECIAL  [RL_G6K2FRT_8P_5V_GR]  373.38 293.12 0 bottom
UNK2K22  G6K-2F-RF-T-5V-SPECIAL  [RL_G6K2FRT_8P_5V_GR]  400.3 229.11 0 bottom
UNK2K23  G6K-2F-RF-T-5V-SPECIAL  [RL_G6K2FRT_8P_5V_GR]  407.16 213.61 0 bottom
UNK2K24  G6K-2F-RF-T-5V-SPECIAL  [RL_G6K2FRT_8P_5V_GR]  393.45 213.36 0 bottom
UNK2K25  G6K-2F-RF-T-5V-SPECIAL  [RL_G6K2FRT_8P_5V_GR]  414.27 245.11 0 bottom
UNK2K26  G6K-2F-RF-T-5V-SPECIAL  [RL_G6K2FRT_8P_5V_GR]  373.13 228.6 0 bottom
UNK2K27  G6K-2F-RF-T-5V-SPECIAL  [RL_G6K2FRT_8P_5V_GR]  386.84 228.85 0 bottom
UNK2K28  UA2-5NJ-A-V3  [RL_NECUA2_5V_V3]  479.04 237.49 180 bottom
UNK2K29  G6K-2F-RF-T-5V-SPECIAL  [RL_G6K2FRT_8P_5V_GR]  386.84 245.11 0 bottom
UNK2K30  G6K-2F-RF-T-5V-SPECIAL  [RL_G6K2FRT_8P_5V_GR]  400.3 245.11 0 bottom
UNK2K31  EC2-5NJ-A  [RL_NECEC2_10P_5V]  506.73 294.64 90 bottom
UNK2K33  NC/UA2-5NJ-A-V3  [RL_NECUA2_5V_V3]  455.68 237.74 0 bottom
UNK2K34  EC2-5NJ-A  [RL_NECEC2_10P_5V]  457.2 294.64 90 bottom
UNK2K36  EC2-5NJ-A  [RL_NECEC2_10P_5V]  490.22 294.64 90 bottom
UNK2K37  EC2-5NJ-A  [RL_NECEC2_10P_5V]  457.2 278.13 90 bottom
UNK2K39  EC2-5NJ-A  [RL_NECEC2_10P_5V]  490.22 278.13 90 bottom
UNK2K40  EC2-5NJ-A  [RL_NECEC2_10P_5V]  473.71 294.64 90 bottom
UNK2K42  EC2-5NJ-A  [RL_NECEC2_10P_5V]  473.71 278.13 90 bottom
UNK2K43  G6K-2F-RF-T-5V-SPECIAL  [RL_G6K2FRT_8P_5V_GR]  386.84 261.11 0 bottom
UNK2R1  NC/1M-1-S4  [R0402]  301.23 227.84 180 bottom
UNK2R2  NC/1M-1-S4  [R0402]  298.95 227.84 0 bottom
UNK2R3  NC/100K-1-S4  [R0402]  289.81 130.81 180 bottom
UNK2R4  NC/100K-1-S4  [R0402]  287.27 130.81 180 bottom
UNK2R5  0-5-S4  [R0402]  302.38 272.16 270 bottom
UNK2R6  1M-1-S4  [R0402]  302.38 274.32 270 bottom
UNK2R7  49.9-1-S4  [R0402]  415.95 299.91 180 bottom
UNK2R8  49.9-1-S4  [R0402]  418.1 299.91 180 bottom
UNK2R9  49.9-1-S4  [R0402]  415.95 286.32 180 bottom
UNK2R10  49.9-1-S4  [R0402]  418.1 286.32 180 bottom
UNK2R11  49.9-1-S4  [R0402]  374.8 251.9 180 bottom
UNK2R12  49.9-1-S4  [R0402]  376.95 251.9 180 bottom
UNK2R13  49.9-1-S4  [R0402]  374.8 238.32 180 bottom
UNK2R14  49.9-1-S4  [R0402]  376.95 238.32 180 bottom
UNK2R15  49.9-1-S4  [R0402]  401.98 268.16 180 bottom
UNK2R16  49.9-1-S4  [R0402]  404.13 268.16 180 bottom
UNK2R17  49.9-1-S4  [R0402]  401.98 254.57 180 bottom
UNK2R18  49.9-1-S4  [R0402]  404.13 254.57 180 bottom
UNK2R19  49.9-1-S4  [R0402]  374.8 267.91 180 bottom
UNK2R20  49.9-1-S4  [R0402]  376.95 267.91 180 bottom
UNK2R21  49.9-1-S4  [R0402]  374.8 254.32 180 bottom
UNK2R22  49.9-1-S4  [R0402]  376.95 254.32 180 bottom
UNK2R23  49.9-1-S4  [R0402]  415.7 268.16 180 bottom
UNK2R24  49.9-1-S4  [R0402]  417.84 268.16 180 bottom
UNK2R25  49.9-1-S4  [R0402]  415.7 254.57 180 bottom
UNK2R26  49.9-1-S4  [R0402]  417.84 254.57 180 bottom
UNK2R27  49.9-1-S4  [R0402]  415.95 284.16 180 bottom
UNK2R28  49.9-1-S4  [R0402]  418.1 284.16 180 bottom
UNK2R29  49.9-1-S4  [R0402]  415.95 270.57 180 bottom
UNK2R30  49.9-1-S4  [R0402]  418.1 270.57 180 bottom
UNK2R31  49.9-1-S4  [R0402]  401.98 283.91 180 bottom
UNK2R32  49.9-1-S4  [R0402]  404.13 283.91 180 bottom
UNK2R33  49.9-1-S4  [R0402]  401.98 270.32 180 bottom
UNK2R34  49.9-1-S4  [R0402]  404.13 270.32 180 bottom
UNK2R37  49.9-1-S4  [R0402]  388.52 286.32 180 bottom
UNK2R38  49.9-1-S4  [R0402]  390.66 286.32 180 bottom
UNK2R39  49.9-1-S4  [R0402]  388.52 283.91 180 bottom
UNK2R40  49.9-1-S4  [R0402]  390.66 283.91 180 bottom
UNK2R41  49.9-1-S4  [R0402]  388.52 270.32 180 bottom
UNK2R42  49.9-1-S4  [R0402]  390.66 270.32 180 bottom
UNK2R43  49.9-1-S4  [R0402]  388.52 238.32 180 bottom
UNK2R44  49.9-1-S4  [R0402]  390.66 238.32 180 bottom
UNK2R45  49.9-1-S4  [R0402]  401.98 222.31 180 bottom
UNK2R46  49.9-1-S4  [R0402]  404.13 222.31 180 bottom
UNK2R47  49.9-1-S4  [R0402]  408.84 220.41 180 bottom
UNK2R48  49.9-1-S4  [R0402]  410.98 220.41 180 bottom
UNK2R49  49.9-1-S4  [R0402]  408.84 206.82 180 bottom
UNK2R50  49.9-1-S4  [R0402]  410.98 206.82 180 bottom
UNK2R51  49.9-1-S4  [R0402]  395.12 220.15 180 bottom
UNK2R52  49.9-1-S4  [R0402]  397.27 220.15 180 bottom
UNK2R53  49.9-1-S4  [R0402]  395.12 206.57 180 bottom
UNK2R54  49.9-1-S4  [R0402]  397.27 206.57 180 bottom
UNK2R55  49.9-1-S4  [R0402]  415.95 251.9 180 bottom
UNK2R56  49.9-1-S4  [R0402]  418.1 251.9 180 bottom
UNK2R57  49.9-1-S4  [R0402]  415.95 238.32 180 bottom
UNK2R58  49.9-1-S4  [R0402]  418.1 238.32 180 bottom
UNK2R59  49.9-1-S4  [R0402]  374.8 235.39 180 bottom
UNK2R60  49.9-1-S4  [R0402]  376.95 235.39 180 bottom
UNK2R61  49.9-1-S4  [R0402]  374.8 221.81 180 bottom
UNK2R62  49.9-1-S4  [R0402]  376.95 221.81 180 bottom
UNK2R63  49.9-1-S4  [R0402]  401.98 251.9 180 bottom
UNK2R64  49.9-1-S4  [R0402]  404.13 251.9 180 bottom
UNK2R65  49.9-1-S4  [R0402]  388.52 222.06 180 bottom
UNK2R66  49.9-1-S4  [R0402]  390.66 222.06 180 bottom
UNK2R67  49.9-1-S4  [R0402]  375.06 283.91 180 bottom
UNK2R68  49.9-1-S4  [R0402]  377.2 283.91 180 bottom
UNK2R69  49.9-1-S4  [R0402]  375.06 270.32 180 bottom
UNK2R70  49.9-1-S4  [R0402]  377.2 270.32 180 bottom
UNK2R71  49.9-1-S4  [R0402]  401.98 299.91 180 bottom
UNK2R72  49.9-1-S4  [R0402]  404.13 299.91 180 bottom
UNK2R73  49.9-1-S4  [R0402]  401.98 286.32 180 bottom
UNK2R74  49.9-1-S4  [R0402]  404.13 286.32 180 bottom
UNK2R75  49.9-1-S4  [R0402]  375.06 299.91 180 bottom
UNK2R76  49.9-1-S4  [R0402]  377.2 299.91 180 bottom
UNK2R77  49.9-1-S4  [R0402]  375.06 286.32 180 bottom
UNK2R78  49.9-1-S4  [R0402]  377.2 286.32 180 bottom
